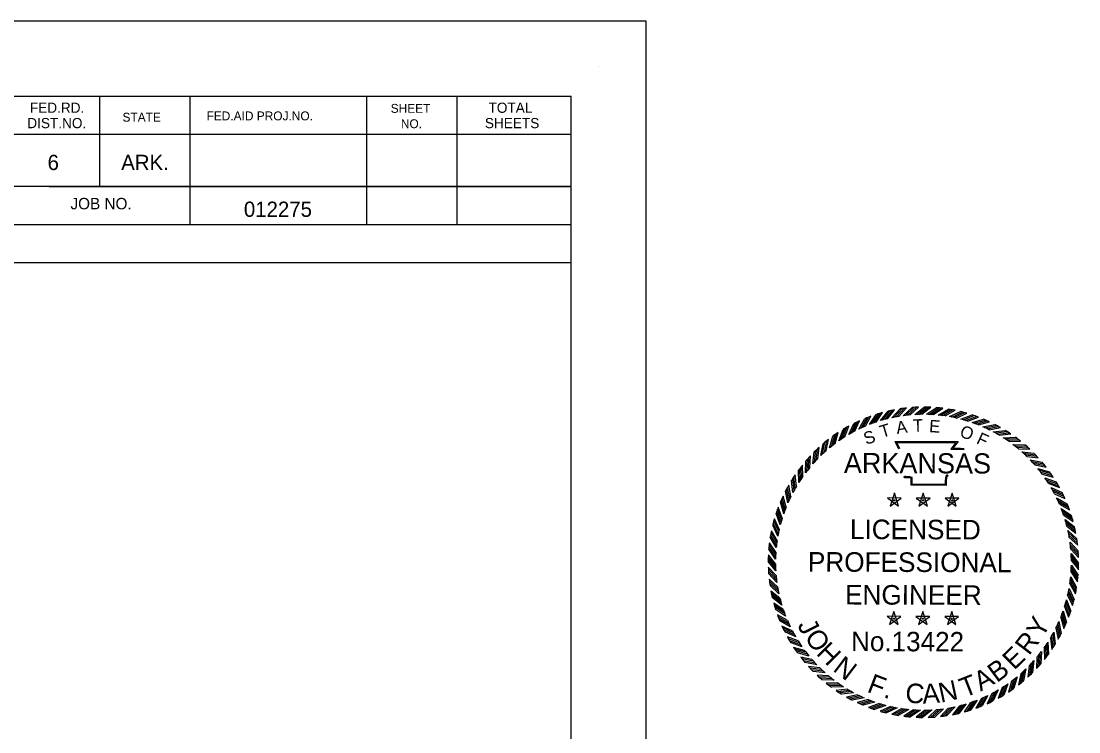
# Model space of a CAD drawing. Extents: x 759422 to 1402138, y 1662254 to 1956530.
# Drawn here: x 1401731 to 1402137.5, y 1956257.2 to 1956530.4 of the extents above; entities that cross this region are included whole.
import ezdxf

# ---------------------------------------------------------------- set-up
doc = ezdxf.new("R2010")
doc.units = 0
doc.layers.add('1', color=7, linetype='Continuous')
doc.layers.add('Default', color=7, linetype='Continuous')

# ---------------------------------------------------------------- blocks, each defined once
blk = doc.blocks.new('STAR')
at = {"layer": 'Default'}
for p, q in [((0.0587, 0.0188), (-0.059, 0.0189)), ((-0.0589, 0.0188), (0.0363, -0.0505)), ((-0.0001, 0.0615), (-0.0366, -0.0504)), ((-0.0365, -0.0503), (0.0589, 0.0188)), ((-0.0085, 0), (0.009, 0)), ((0.0362, -0.0503), (0, 0.0617)), ((0, 0.0063), (0, -0.0085))]:
    blk.add_line(p, q, dxfattribs=at)
blk = doc.blocks.new('RP')
at = {"layer": 'Default'}
for p, q in [((-0.0781, 1.2656), (0.003, 1.33)), ((-0.058, 1.2667), (0.0216, 1.3299)), ((-0.0375, 1.2674), (0.0405, 1.3294)), ((-0.0176, 1.2679), (0.059, 1.3287))]:
    blk.add_line(p, q, dxfattribs=at)
for radius, start, end in [(1.33, 87.45624, 89.86992), (1.268, 90.79335, 93.53072)]:
    blk.add_arc((0, 0), radius, start, end, dxfattribs=at)

msp = doc.modelspace()

# ---------------------------------------------------------------- linework, layer by layer
at = {"layer": '1'}
for p, q in [((1401953.38, 1956513.05), (1401953.38, 1956513.05)), ((1400347.07, 1956501.52), (1401942.43, 1956501.52)), ((1401761.13, 1956501.52), (1401761.13, 1956466.82)), ((1401795.83, 1956501.52), (1401795.83, 1956452.12)), ((1401863.73, 1956501.52), (1401863.73, 1956452.12)), ((1401898.43, 1956501.52), (1401898.43, 1956452.12)), ((1401942.43, 1955459.2), (1401942.43, 1956501.52)), ((1401942.43, 1956486.82), (1401726.93, 1956486.82)), ((1401942.43, 1956486.92), (1401942.43, 1956486.92)), ((1401942.43, 1956466.82), (1401726.93, 1956466.82)), ((1401741.73, 1956466.82), (1401942.43, 1956466.82)), ((1401942.43, 1956452.12), (1401531.13, 1956452.12)), ((1401726.93, 1956437.52), (1401942.43, 1956437.52))]:
    msp.add_line(p, q, dxfattribs=at)
msp.add_lwpolyline([(1401971.27, 1956530.36), (1400271.27, 1956530.36), (1400271.27, 1955430.36), (1401971.27, 1955430.36)], close=True, dxfattribs=at)
at = {"layer": 'Default'}
for points in [[(1402068.36, 1956365.8), (1402066.98, 1956368.82), (1402091.1, 1956368.76), (1402089.08, 1956366.23), (1402090.72, 1956366.25), (1402092.09, 1956366.26), (1402093.46, 1956366.1)], [(1402068.71, 1956365.96), (1402067.57, 1956368.44), (1402090.31, 1956368.38), (1402088.28, 1956365.84), (1402090.72, 1956365.86), (1402092.07, 1956365.88), (1402093.41, 1956365.72)], [(1402087.26, 1956355.62), (1402086.84, 1956355.29), (1402086.71, 1956354.79), (1402086.57, 1956353.54), (1402086.56, 1956351.87), (1402073.09, 1956351.92), (1402073.1, 1956354.17), (1402073.1, 1956354.67), (1402072.56, 1956354.84), (1402070.64, 1956354.85), (1402070.3, 1956355.37)], [(1402087.02, 1956355.92), (1402086.51, 1956355.51), (1402086.33, 1956354.86), (1402086.18, 1956353.56), (1402086.18, 1956352.26), (1402073.48, 1956352.3), (1402073.48, 1956354.17), (1402073.48, 1956354.95), (1402072.61, 1956355.22), (1402070.85, 1956355.23), (1402070.62, 1956355.57)]]:
    msp.add_lwpolyline(points, dxfattribs=at)

# ---------------------------------------------------------------- block references
for name, p, xscale, yscale, rotation in [('RP', (1402077.8, 1956322.35), 44.855502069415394, 44.85550206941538, 13.304199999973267), ('RP', (1402077.8, 1956322.35), 44.855502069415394, 44.855502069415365, 8.804199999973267), ('RP', (1402077.8, 1956322.35), 44.85550206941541, 44.85550206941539, 4.304199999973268), ('RP', (1402077.8, 1956322.35), 44.8555020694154, 44.85550206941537, -0.19580000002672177), ('RP', (1402077.8, 1956322.35), 44.8555020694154, 44.85550206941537, -4.695800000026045), ('RP', (1402077.8, 1956322.35), 44.85550206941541, 44.85550206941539, -9.195800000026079), ('RP', (1402077.8, 1956322.35), 44.855502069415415, 44.85550206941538, -13.695800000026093), ('RP', (1402077.8, 1956322.35), 44.85550206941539, 44.85550206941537, 22.30419999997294), ('RP', (1402077.8, 1956322.35), 44.855502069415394, 44.85550206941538, 17.80419999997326), ('RP', (1402077.8, 1956322.35), 44.85550206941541, 44.85550206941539, -18.195800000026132), ('RP', (1402077.8, 1956322.35), 44.8555020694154, 44.85550206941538, -22.69580000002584), ('RP', (1402077.8, 1956322.35), 44.855502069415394, 44.85550206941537, -27.19580000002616), ('RP', (1402077.8, 1956322.35), 44.85550206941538, 44.85550206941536, 31.30419999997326), ('RP', (1402077.8, 1956322.35), 44.855502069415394, 44.855502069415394, 26.804199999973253), ('RP', (1402077.8, 1956322.35), 44.85550206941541, 44.8555020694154, -31.695800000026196), ('RP', (1402077.8, 1956322.35), 44.85550206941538, 44.85550206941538, 40.304199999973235), ('RP', (1402077.8, 1956322.35), 44.85550206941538, 44.85550206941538, 35.80419999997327), ('RP', (1402077.8, 1956322.35), 44.8555020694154, 44.855502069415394, -36.195800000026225), ('RP', (1402077.8, 1956322.35), 44.85550206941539, 44.8555020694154, -40.69580000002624), ('RP', (1402077.8, 1956322.35), 44.85550206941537, 44.855502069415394, 44.80419999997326), ('RP', (1402077.8, 1956322.35), 44.85550206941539, 44.85550206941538, -45.195800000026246), ('RP', (1402077.8, 1956322.35), 44.8555020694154, 44.8555020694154, 49.304199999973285), ('RP', (1402077.8, 1956322.35), 44.85550206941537, 44.85550206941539, -49.695800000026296), ('RP', (1402077.8, 1956322.35), 44.8555020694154, 44.85550206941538, 53.804199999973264), ('RP', (1402077.8, 1956322.35), 44.85550206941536, 44.855502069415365, -54.1958000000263), ('RP', (1402077.8, 1956322.35), 44.85550206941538, 44.85550206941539, 58.304199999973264), ('RP', (1402077.8, 1956322.35), 44.85550206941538, 44.85550206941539, -58.695800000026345), ('RP', (1402077.8, 1956322.35), 44.85550206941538, 44.855502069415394, 62.804199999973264), ('STAR', (1402066.61, 1956346.21), 44.8555020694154, 44.85550206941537, -0.19580000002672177), ('STAR', (1402077.71, 1956346.17), 44.8555020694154, 44.85550206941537, -0.19580000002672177), ('STAR', (1402088.81, 1956346.13), 44.8555020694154, 44.85550206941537, -0.19580000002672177), ('RP', (1402077.8, 1956322.35), 44.85550206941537, 44.85550206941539, -63.19580000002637), ('RP', (1402077.8, 1956322.35), 44.85550206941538, 44.8555020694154, 67.30419999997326), ('RP', (1402077.8, 1956322.35), 44.85550206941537, 44.85550206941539, -67.6958000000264), ('RP', (1402077.8, 1956322.35), 44.85550206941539, 44.855502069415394, 71.80419999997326), ('RP', (1402077.8, 1956322.35), 44.85550206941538, 44.8555020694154, -72.19580000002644), ('RP', (1402077.8, 1956322.35), 44.85550206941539, 44.85550206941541, 76.30419999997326), ('RP', (1402077.8, 1956322.35), 44.85550206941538, 44.85550206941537, -76.69580000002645), ('RP', (1402077.8, 1956322.35), 44.85550206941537, 44.8555020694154, 80.80419999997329), ('RP', (1402077.8, 1956322.35), 44.85550206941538, 44.8555020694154, -81.19580000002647), ('RP', (1402077.8, 1956322.35), 44.855502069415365, 44.85550206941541, 85.30419999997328), ('RP', (1402077.8, 1956322.35), 44.85550206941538, 44.855502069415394, -85.69580000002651), ('RP', (1402077.8, 1956322.35), 44.85550206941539, 44.85550206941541, 89.80419999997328), ('RP', (1402077.8, 1956322.35), 44.85550206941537, 44.8555020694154, -90.19580000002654), ('RP', (1402077.8, 1956322.35), 44.85550206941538, 44.85550206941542, 94.30419999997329), ('RP', (1402077.8, 1956322.35), 44.85550206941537, 44.85550206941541, -94.69580000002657), ('RP', (1402077.8, 1956322.35), 44.85550206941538, 44.855502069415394, 98.8041999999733), ('RP', (1402077.8, 1956322.35), 44.85550206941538, 44.855502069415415, -99.19580000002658), ('RP', (1402077.8, 1956322.35), 44.85550206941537, 44.8555020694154, 103.30419999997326), ('RP', (1402077.8, 1956322.35), 44.85550206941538, 44.8555020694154, -103.69580000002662), ('RP', (1402077.8, 1956322.35), 44.85550206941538, 44.85550206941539, -108.19580000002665), ('RP', (1402077.8, 1956322.35), 44.85550206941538, 44.855502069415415, 107.80419999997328), ('RP', (1402077.8, 1956322.35), 44.85550206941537, 44.85550206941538, 112.3041999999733), ('STAR', (1402066.46, 1956300.71), 44.8555020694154, 44.85550206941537, -0.19580000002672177), ('STAR', (1402077.56, 1956300.68), 44.8555020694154, 44.85550206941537, -0.19580000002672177), ('STAR', (1402088.65, 1956300.64), 44.8555020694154, 44.85550206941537, -0.19580000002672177), ('RP', (1402077.8, 1956322.35), 44.85550206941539, 44.855502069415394, -112.69580000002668), ('RP', (1402077.8, 1956322.35), 44.85550206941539, 44.8555020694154, 116.80419999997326), ('RP', (1402077.8, 1956322.35), 44.85550206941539, 44.85550206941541, -117.19580000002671), ('RP', (1402077.8, 1956322.35), 44.855502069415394, 44.85550206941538, 121.30419999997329), ('RP', (1402077.8, 1956322.35), 44.8555020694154, 44.8555020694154, -126.19580000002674), ('RP', (1402077.8, 1956322.35), 44.85550206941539, 44.8555020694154, -121.69580000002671), ('RP', (1402077.8, 1956322.35), 44.85550206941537, 44.85550206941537, 125.80419999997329), ('RP', (1402077.8, 1956322.35), 44.85550206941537, 44.85550206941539, 130.3041999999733), ('RP', (1402077.8, 1956322.35), 44.85550206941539, 44.85550206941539, -130.6958000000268), ('RP', (1402077.8, 1956322.35), 44.855502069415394, 44.85550206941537, 134.80419999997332), ('RP', (1402077.8, 1956322.35), 44.85550206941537, 44.855502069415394, -135.19580000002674), ('RP', (1402077.8, 1956322.35), 44.85550206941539, 44.85550206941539, 139.30419999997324), ('RP', (1402077.8, 1956322.35), 44.85550206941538, 44.85550206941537, -139.69580000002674), ('RP', (1402077.8, 1956322.35), 44.85550206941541, 44.855502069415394, 143.8041999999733), ('RP', (1402077.8, 1956322.35), 44.85550206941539, 44.85550206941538, 148.3041999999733), ('RP', (1402077.8, 1956322.35), 44.85550206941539, 44.85550206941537, -148.69580000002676), ('RP', (1402077.8, 1956322.35), 44.85550206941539, 44.855502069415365, -144.19580000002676), ('RP', (1402077.8, 1956322.35), 44.8555020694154, 44.855502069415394, 152.8041999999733), ('RP', (1402077.8, 1956322.35), 44.85550206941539, 44.85550206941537, -153.1958000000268), ('RP', (1402077.8, 1956322.35), 44.8555020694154, 44.85550206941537, 157.3041999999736), ('RP', (1402077.8, 1956322.35), 44.85550206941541, 44.85550206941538, 161.80419999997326), ('RP', (1402077.8, 1956322.35), 44.855502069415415, 44.85550206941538, 166.3041999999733), ('RP', (1402077.8, 1956322.35), 44.855502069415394, 44.85550206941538, -166.69580000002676), ('RP', (1402077.8, 1956322.35), 44.855502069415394, 44.85550206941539, -162.19580000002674), ('RP', (1402077.8, 1956322.35), 44.8555020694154, 44.85550206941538, -157.6958000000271), ('RP', (1402077.8, 1956322.35), 44.8555020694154, 44.855502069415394, 170.8041999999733), ('RP', (1402077.8, 1956322.35), 44.8555020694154, 44.85550206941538, 175.3041999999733), ('RP', (1402077.8, 1956322.35), 44.85550206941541, 44.85550206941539, 179.8041999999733), ('RP', (1402077.8, 1956322.35), 44.8555020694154, 44.85550206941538, -175.69580000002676), ('RP', (1402077.8, 1956322.35), 44.85550206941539, 44.85550206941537, -171.19580000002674)]:
    msp.add_blockref(name, p, dxfattribs=dict(at, xscale=xscale, yscale=yscale, rotation=rotation))

# ---------------------------------------------------------------- texts
at = {"layer": '1'}
for s, height, p in [('FED.RD.', 3.91, (1401734.32, 1956495.12)), ('TOTAL', 3.91, (1401910.62, 1956495.12)), ('STATE', 3.42, (1401769.92, 1956491.72)), ('FED.AID PROJ.NO.', 3.42, (1401802.22, 1956492.22)), ('SHEET', 3.42, (1401873.02, 1956495.12)), ('DIST.NO.', 3.91, (1401733.32, 1956489.22)), ('NO.', 3.42, (1401876.92, 1956489.22)), ('SHEETS', 3.91, (1401909.22, 1956489.22)), ('6', 5.86, (1401741.12, 1956473.12)), ('ARK.', 5.861, (1401769.42, 1956473.12)), ('JOB NO.', 4.396, (1401749.92, 1956458.02)), ('012275', 5.862, (1401816.58, 1956455.12))]:
    msp.add_text(s, height=height, dxfattribs=at).set_placement(p)
at = {"layer": 'Default'}
for s, height, rotation, p in [('T', 4.76, 1.2831, (1402073.8, 1956372.54)), ('E', 4.76, 356.4762, (1402079.89, 1956372.37)), ('S', 4.76, 19.5768, (1402055.8, 1956367.42)), ('T', 4.76, 16.7057, (1402061.86, 1956370.12)), ('A', 4.76, 8.483, (1402067.65, 1956371.61)), ('O', 4.76, 341.026, (1402091.44, 1956370.7)), ('F', 4.76, 335.167, (1402097.84, 1956368.17)), ('ARKANSAS', 7.767, 359.8042, (1402047.21, 1956356.63)), ('LICENSED', 7.52, 359.8042, (1402049.54, 1956331.27)), ('PROFESSIONAL', 7.5196, 359.8042, (1402033.38, 1956318.75)), ('ENGINEER', 7.52, 359.8042, (1402047.66, 1956306.12)), ('J', 7.52, 297.2813, (1402029.19, 1956298.19)), ('Y', 7.52, 62.5392, (1402123.64, 1956292.84)), ('O', 7.52, 304.1899, (1402031.85, 1956293.57)), ('No.13422', 7.49, 359.8042, (1402049.97, 1956288.19)), ('H', 7.52, 314.7447, (1402036.29, 1956287.1)), ('R', 7.52, 52.7437, (1402118.39, 1956286.22)), ('E', 7.52, 44.306, (1402112.66, 1956280.62)), ('N', 7.52, 322.9417, (1402042.64, 1956280.81)), ('B', 7.52, 36.505, (1402106.02, 1956275.84)), ('F', 7.52, 339.0288, (1402055.76, 1956272.66)), ('T', 7.52, 21.4329, (1402093.52, 1956270.21)), ('A', 7.52, 28.8562, (1402099.78, 1956272.56)), ('C', 7.52, 356.1028, (1402070.68, 1956268.44)), ('A', 7.52, 3.9092, (1402077.58, 1956267.95)), ('N', 7.52, 12.0703, (1402084.45, 1956268.33)), ('.', 7.52, 344.7037, (1402062.18, 1956270.44))]:
    msp.add_text(s, height=height, rotation=rotation, dxfattribs=at).set_placement(p)

doc.saveas('drawing.dxf')
